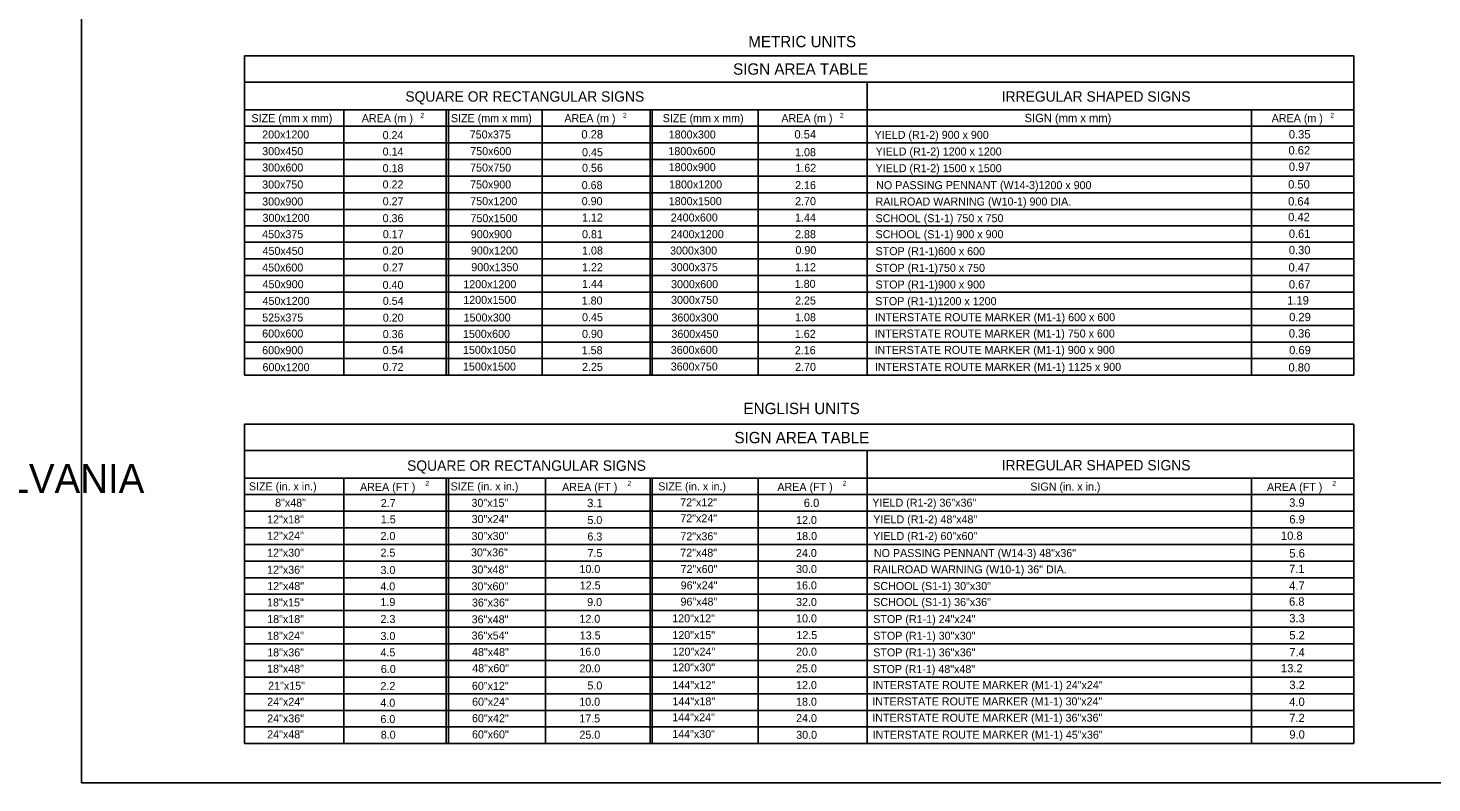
# Model space of a CAD drawing. Extents: x 644358 to 648627, y 294594 to 295782.
# Drawn here: x 645219 to 645745, y 295203 to 295486 of the extents above; entities that cross this region are included whole.
import ezdxf

# ---------------------------------------------------------------- set-up
doc = ezdxf.new("R2010")
doc.units = 0
for name, color, linetype in [('1', 7, 'Continuous'), ('2', 7, 'Continuous'), ('4', 7, 'Continuous')]:
    doc.layers.add(name, color=color, linetype=linetype)

msp = doc.modelspace()

# ---------------------------------------------------------------- linework, layer by layer
at = {"layer": '1'}
for p, q in [((645239.31, 295766.63), (645239.31, 295202.63)), ((646025.31, 295202.63), (645239.31, 295202.63)), ((645239.31, 295202.63), (645825.31, 295202.63))]:
    msp.add_line(p, q, dxfattribs=at)
at = {"layer": '2'}
for p, q in [((645300.44, 295475.25), (645300.44, 295355.5)), ((645716.19, 295475.25), (645300.44, 295475.25)), ((645716.19, 295355.5), (645716.19, 295475.25)), ((645716.19, 295465.37), (645300.44, 295465.37)), ((645533.81, 295465.37), (645533.81, 295355.5)), ((645300.44, 295455), (645716.19, 295455)), ((645337.69, 295455), (645337.69, 295355.5)), ((645376.06, 295455), (645376.06, 295355.5)), ((645376.94, 295455), (645376.94, 295355.5)), ((645411.94, 295455), (645411.94, 295355.5)), ((645452.44, 295455), (645452.44, 295355.5)), ((645453.19, 295455), (645453.19, 295355.5)), ((645492.94, 295455), (645492.94, 295355.5)), ((645677.81, 295355.5), (645677.81, 295455)), ((645300.44, 295448.87), (645716.19, 295448.87)), ((645300.44, 295442.62), (645716.19, 295442.62)), ((645300.44, 295436.37), (645716.19, 295436.37)), ((645300.44, 295430.12), (645716.19, 295430.12)), ((645300.44, 295423.87), (645716.19, 295423.87)), ((645300.44, 295417.62), (645716.19, 295417.62)), ((645300.44, 295411.5), (645716.19, 295411.5)), ((645300.44, 295405.37), (645716.19, 295405.37)), ((645300.44, 295399.12), (645716.19, 295399.12)), ((645300.44, 295392.87), (645716.19, 295392.87)), ((645300.44, 295386.62), (645716.19, 295386.62)), ((645300.44, 295380.37), (645716.19, 295380.37)), ((645300.44, 295374.12), (645716.19, 295374.12)), ((645533.81, 295374.12), (645716.19, 295374.12)), ((645300.44, 295367.87), (645716.19, 295367.87)), ((645716.19, 295367.87), (645533.81, 295367.87)), ((645300.44, 295361.75), (645716.19, 295361.75)), ((645300.44, 295355.5), (645533.81, 295355.5)), ((645716.19, 295355.5), (645533.81, 295355.5)), ((645300.44, 295337.19), (645300.44, 295217.44)), ((645716.19, 295337.19), (645300.44, 295337.19)), ((645716.19, 295217.44), (645716.19, 295337.19)), ((645716.19, 295327.31), (645300.44, 295327.31)), ((645533.81, 295327.31), (645533.81, 295217.44)), ((645300.44, 295316.94), (645716.19, 295316.94)), ((645337.69, 295316.94), (645337.69, 295217.44)), ((645376.06, 295316.94), (645376.06, 295217.44)), ((645376.94, 295316.94), (645376.94, 295217.44)), ((645413.24, 295316.94), (645413.24, 295217.44)), ((645452.44, 295316.94), (645452.44, 295217.44)), ((645453.19, 295316.94), (645453.19, 295217.44)), ((645492.94, 295316.94), (645492.94, 295217.44)), ((645677.81, 295217.44), (645677.81, 295316.94)), ((645300.44, 295310.81), (645716.19, 295310.81)), ((645300.44, 295304.56), (645716.19, 295304.56)), ((645300.44, 295298.31), (645716.19, 295298.31)), ((645300.44, 295292.06), (645716.19, 295292.06)), ((645300.44, 295285.81), (645716.19, 295285.81)), ((645300.44, 295279.56), (645716.19, 295279.56)), ((645300.44, 295273.44), (645716.19, 295273.44)), ((645300.44, 295267.31), (645716.19, 295267.31)), ((645300.44, 295261.06), (645716.19, 295261.06)), ((645300.44, 295254.81), (645716.19, 295254.81)), ((645300.44, 295248.56), (645716.19, 295248.56)), ((645300.44, 295242.31), (645716.19, 295242.31)), ((645300.44, 295236.06), (645716.19, 295236.06)), ((645533.81, 295236.06), (645716.19, 295236.06)), ((645300.44, 295229.81), (645716.19, 295229.81)), ((645716.19, 295229.81), (645533.81, 295229.81)), ((645300.44, 295223.69), (645716.19, 295223.69)), ((645300.44, 295217.44), (645533.81, 295217.44)), ((645716.19, 295217.44), (645533.81, 295217.44))]:
    msp.add_line(p, q, dxfattribs=at)
at = {"layer": '4'}
for p, q in [((645698.96, 295394.5), (645698.96, 295394.5)), ((645698.96, 295388.25), (645698.96, 295388.25)), ((645698.96, 295382), (645698.96, 295382)), ((645698.96, 295375.75), (645698.96, 295375.75)), ((645698.96, 295369.62), (645698.96, 295369.62)), ((645698.96, 295363.37), (645698.96, 295363.37)), ((645698.96, 295357.12), (645698.96, 295357.12)), ((645354.89, 295231.31), (645354.89, 295231.31)), ((645354.89, 295225.06), (645354.89, 295225.06)), ((645354.89, 295218.81), (645354.89, 295218.81))]:
    msp.add_line(p, q, dxfattribs=at)

# ---------------------------------------------------------------- texts
at = {"layer": '1'}
msp.add_text('COMMONWEALTH OF PENNSYLVANIA', height=10.7828, dxfattribs=at).set_placement((644996.9, 295311.36))
at = {"layer": '4'}
for s, height, p in [('METRIC UNITS', 4.25, (645489.24, 295478.46)), ('SIGN AREA TABLE', 4.25, (645483.55, 295468.17)), ('SQUARE OR RECTANGULAR SIGNS', 3.8872, (645360.71, 295458.05)), ('IRREGULAR SHAPED SIGNS', 3.8872, (645584.22, 295458.05)), ('SIZE (mm x mm)', 3, (645303.06, 295450.37)), ('AREA (m )', 3, (645344.39, 295450.37)), ('2', 1.8, (645366.34, 295452.06)), ('SIZE (mm x mm)', 3, (645377.81, 295450.37)), ('AREA (m )', 3, (645420.31, 295450.37)), ('2', 1.8, (645442.26, 295452.06)), ('SIZE (mm x mm)', 3, (645457.19, 295450.37)), ('AREA (m )', 3, (645501.66, 295450.37)), ('2', 1.8, (645523.61, 295452.06)), ('SIGN (mm x mm)', 3.1252, (645592.81, 295450.37)), ('AREA (m )', 3, (645685.43, 295450.37)), ('2', 1.8, (645707.38, 295452.06)), ('200x1200', 3, (645307.06, 295444.25)), ('0.24', 3, (645352.2, 295444)), ('750x375', 3, (645384.85, 295444.25)), ('0.28', 3.125, (645426.69, 295444.25)), ('1800x300', 3, (645459.44, 295444.25)), ('0.54', 3.125, (645506.54, 295444.25)), ('YIELD (R1-2) 900 x 900 ', 3, (645536.56, 295444.12)), ('0.35', 3.125, (645691.83, 295444.25)), ('0.62', 3.125, (645691.71, 295438.25)), ('300x450', 3, (645307.06, 295438)), ('0.14', 3, (645352.2, 295437.84)), ('750x600', 3, (645385.04, 295438)), ('0.45', 3, (645426.94, 295437.62)), ('1800x600', 3, (645459.31, 295438)), ('1.08', 3, (645506.79, 295437.62)), ('YIELD (R1-2) 1200 x 1200 ', 3, (645536.94, 295437.87)), ('300x600', 3, (645307.06, 295431.87)), ('0.18', 3, (645352.2, 295431.62)), ('750x750', 3, (645384.99, 295431.83)), ('0.56', 3, (645426.94, 295431.75)), ('1800x900', 3, (645459.44, 295432)), ('1.62', 3, (645506.9, 295431.75)), ('YIELD (R1-2) 1500 x 1500 ', 3, (645536.94, 295431.62)), ('0.97', 3.125, (645691.83, 295432.12)), ('300x750', 3, (645307.06, 295425.5)), ('0.22', 3, (645352.19, 295425.52)), ('750x900', 3, (645384.99, 295425.5)), ('0.68', 3, (645426.81, 295425.25)), ('1800x1200', 3, (645459.56, 295425.5)), ('2.16', 3, (645506.8, 295425.25)), ('NO PASSING PENNANT (W14-3)1200 x 900 ', 3, (645537.19, 295425.25)), ('0.50', 3.125, (645691.58, 295425.5)), ('300x900', 3, (645307.06, 295419.12)), ('0.27', 3, (645352.22, 295419.2)), ('750x1200', 3, (645385.04, 295419.25)), ('0.90', 3, (645426.81, 295419.25)), ('1800x1500', 3, (645459.44, 295419.25)), ('2.70', 3, (645506.8, 295419.25)), ('RAILROAD WARNING (W10-1) 900 DIA.', 3, (645536.94, 295419.12)), ('0.64', 3.125, (645691.58, 295419.12)), ('300x1200', 3, (645307.19, 295413)), ('0.36', 3, (645352.2, 295412.87)), ('750x1500', 3, (645385.13, 295412.86)), ('1.12', 3, (645426.94, 295413.12)), ('2400x600', 3, (645460.19, 295413.12)), ('1.44', 3, (645506.79, 295413.12)), ('SCHOOL (S1-1) 750 x 750 ', 3, (645536.94, 295412.87)), ('0.42', 3.125, (645691.58, 295413.25)), ('450x375', 3, (645307.06, 295406.87)), ('0.17', 3, (645352.26, 295406.87)), ('900x900', 3, (645385.25, 295406.87)), ('0.81', 3, (645426.94, 295406.87)), ('2400x1200', 3, (645460.19, 295406.87)), ('2.88', 3, (645506.79, 295406.87)), ('SCHOOL (S1-1) 900 x 900 ', 3, (645536.94, 295406.87)), ('0.61', 3.125, (645691.83, 295407)), ('450x450', 3, (645307.19, 295400.62)), ('0.20', 3, (645352.19, 295400.75)), ('900x1200', 3, (645385.29, 295400.75)), ('1.08', 3, (645426.94, 295400.75)), ('3000x300', 3, (645459.94, 295400.75)), ('0.90', 3, (645506.93, 295400.88)), ('STOP (R1-1)600 x 600 ', 3, (645536.94, 295400.5)), ('0.30', 3.125, (645691.83, 295400.87)), ('450x600', 3, (645307.06, 295394.37)), ('0.27', 3, (645352.26, 295394.39)), ('900x1350', 3, (645385.43, 295394.5)), ('1.22', 3, (645426.94, 295394.5)), ('3000x375', 3, (645460.19, 295394.5)), ('1.12', 3, (645506.79, 295394.5)), ('STOP (R1-1)750 x 750', 3, (645536.94, 295394.25)), ('0.47', 3.125, (645691.71, 295394.37)), ('450x900', 3, (645307.19, 295388.12)), ('0.40', 3, (645352.19, 295387.87)), ('1200x1200', 3, (645382.44, 295388.12)), ('1.44', 3, (645426.94, 295388.25)), ('3000x600', 3, (645460.31, 295388.12)), ('1.80', 3, (645506.67, 295388.25)), ('STOP (R1-1)900 x 900 ', 3, (645536.94, 295388)), ('0.67', 3.125, (645691.83, 295388)), ('450x1200', 3, (645307.19, 295381.87)), ('0.54', 3, (645352.26, 295381.88)), ('1200x1500', 3, (645382.44, 295382.25)), ('1.80', 3, (645426.81, 295382)), ('3000x750', 3, (645460.31, 295382.25)), ('2.25', 3, (645506.79, 295382)), ('STOP (R1-1)1200 x 1200', 3, (645536.81, 295381.75)), ('1.19', 3.125, (645691.21, 295382)), ('525x375', 3, (645307.06, 295375.62)), ('0.20', 3, (645352.26, 295375.57)), ('1500x300', 3, (645382.56, 295375.62)), ('0.45', 3, (645426.94, 295375.75)), ('3600x300', 3, (645460.44, 295375.62)), ('1.08', 3, (645506.79, 295375.75)), ('INTERSTATE ROUTE MARKER (M1-1) 600 x 600 ', 3, (645536.69, 295375.75)), ('0.29', 3.125, (645691.96, 295375.75)), ('600x600', 3, (645307.06, 295369.62)), ('0.36', 3, (645352.24, 295369.41)), ('1500x600', 3, (645382.31, 295369.5)), ('0.90', 3, (645426.93, 295369.5)), ('3600x450', 3, (645460.44, 295369.5)), ('1.62', 3, (645506.69, 295369.5)), ('INTERSTATE ROUTE MARKER (M1-1) 750 x 600 ', 3, (645536.56, 295369.62)), ('0.36', 3.125, (645691.83, 295369.62)), ('600x900', 3, (645307.06, 295363.37)), ('0.54', 3, (645352.22, 295363.39)), ('1500x1050', 3, (645382.31, 295363.5)), ('1.58', 3, (645426.81, 295363.37)), ('3600x600', 3, (645460.19, 295363.5)), ('2.16', 3, (645506.69, 295363.37)), ('INTERSTATE ROUTE MARKER (M1-1) 900 x 900 ', 3, (645536.56, 295363.5)), ('0.69', 3.125, (645691.96, 295363.37)), ('600x1200', 3, (645307.19, 295357)), ('0.72', 3, (645352.22, 295357.09)), ('1500x1500', 3, (645382.31, 295357.25)), ('2.25', 3, (645426.94, 295357.12)), ('3600x750', 3, (645460.19, 295357.25)), ('2.70', 3, (645506.8, 295357.12)), ('INTERSTATE ROUTE MARKER (M1-1) 1125 x 900 ', 3, (645536.69, 295357.12)), ('0.80', 3.125, (645691.71, 295356.87)), ('ENGLISH UNITS', 4.25, (645487.45, 295340.91)), ('SIGN AREA TABLE', 4.25, (645484.06, 295329.98)), ('SQUARE OR RECTANGULAR SIGNS', 3.8872, (645361.36, 295319.67)), ('IRREGULAR SHAPED SIGNS', 3.8872, (645584.22, 295319.81)), ('SIZE (in. x in.)', 3, (645302.07, 295312.31)), ('AREA (FT )', 3, (645343.73, 295312.11)), ('2', 1.8, (645368.22, 295314.08)), ('SIZE (in. x in.)', 3, (645377.67, 295312.31)), ('AREA (FT )', 3, (645419.46, 295312.11)), ('2', 1.8, (645443.95, 295314.08)), ('SIZE (in. x in.)', 3, (645455.5, 295312.31)), ('AREA (FT )', 3, (645500.16, 295312.11)), ('2', 1.8, (645524.65, 295314.08)), ('SIGN (in. x in.)', 3, (645594.95, 295312.24)), ('AREA (FT )', 3, (645683.68, 295312.11)), ('2', 1.8, (645708.17, 295314.08)), ('8"x48"', 3, (645311.91, 295306.19)), ('2.7', 3, (645351.5, 295306.07)), ('30"x15"', 3, (645385.5, 295306.15)), ('3.1', 3.125, (645428.86, 295306.02)), ('72"x12"', 3, (645463.75, 295306.32)), ('6.0', 3.125, (645510.05, 295306.08)), ('YIELD (R1-2) 36"x36" ', 3, (645535.72, 295306.2)), ('3.9', 3.125, (645691.98, 295306.18)), ('12"x18"', 3, (645308.91, 295299.94)), ('1.5', 3, (645351.53, 295299.96)), ('30"x24"', 3, (645385.56, 295300.07)), ('5.0', 3, (645428.96, 295299.7)), ('72"x24"', 3, (645463.77, 295300.36)), ('12.0', 3, (645507.16, 295299.7)), ('YIELD (R1-2) 48"x48" ', 3, (645536.09, 295299.95)), ('6.9', 3.125, (645692.01, 295299.9)), ('12"x24"', 3, (645308.91, 295293.81)), ('2.0', 3, (645351.4, 295293.7)), ('30"x30"', 3, (645385.51, 295293.72)), ('6.3', 3, (645428.96, 295293.52)), ('72"x36"', 3, (645463.79, 295293.61)), ('18.0', 3, (645507.21, 295293.7)), ('YIELD (R1-2) 60"x60" ', 3, (645536.09, 295293.7)), ('10.8', 3.125, (645688.89, 295293.77)), ('12"x30"', 3, (645308.91, 295287.44)), ('2.5', 3, (645351.4, 295287.45)), ('30"x36"', 3, (645385.33, 295287.57)), ('7.5', 3, (645429, 295287.32)), ('72"x48"', 3, (645463.76, 295287.45)), ('24.0', 3, (645507.12, 295287.32)), ('NO PASSING PENNANT (W14-3) 48"x36" ', 3, (645536.34, 295287.32)), ('5.6', 3.125, (645692.03, 295287.15)), ('12"x36"', 3, (645308.91, 295281.06)), ('3.0', 3, (645351.39, 295280.95)), ('30"x48"', 3, (645385.49, 295281.15)), ('10.0', 3, (645425.97, 295281.32)), ('72"x60"', 3, (645463.88, 295281.33)), ('30.0', 3, (645507.17, 295281.32)), ('RAILROAD WARNING (W10-1) 36" DIA.', 3, (645536.09, 295281.2)), ('7.1', 3.125, (645691.93, 295281.34)), ('12.5', 3, (645426.09, 295275.2)), ('96"x24"', 3, (645463.9, 295275.21)), ('16.0', 3, (645507.16, 295275.2)), ('12"x48"', 3, (645308.96, 295274.94)), ('4.0', 3, (645351.35, 295274.81)), ('30"x60"', 3, (645385.49, 295274.85)), ('SCHOOL (S1-1) 30"x30" ', 3, (645536.09, 295274.95)), ('4.7', 3.125, (645691.98, 295275.04)), ('18"x15"', 3, (645308.88, 295268.81)), ('1.9', 3, (645351.38, 295268.95)), ('36"x36"', 3, (645385.68, 295268.77)), ('9.0', 3, (645428.87, 295268.95)), ('96"x48"', 3, (645463.85, 295269.09)), ('32.0', 3, (645507.16, 295268.95)), ('SCHOOL (S1-1) 36"x36" ', 3, (645536.09, 295268.95)), ('6.8', 3.125, (645691.92, 295269.07)), ('18"x18"', 3, (645308.94, 295262.56)), ('2.3', 3, (645351.4, 295262.58)), ('36"x48"', 3, (645385.56, 295262.47)), ('12.0', 3, (645425.96, 295262.67)), ('120"x12"', 3, (645460.74, 295262.83)), ('10.0', 3, (645507.17, 295262.82)), ('STOP (R1-1) 24"x24" ', 3, (645536.09, 295262.57)), ('3.3', 3.125, (645692.01, 295262.81)), ('18"x24"', 3, (645308.91, 295256.31)), ('3.0', 3, (645351.4, 295256.2)), ('36"x54"', 3, (645385.56, 295256.4)), ('13.5', 3, (645426.09, 295256.42)), ('120"x15"', 3, (645460.79, 295256.58)), ('12.5', 3, (645507.29, 295256.57)), ('STOP (R1-1) 30"x30"', 3, (645536.09, 295256.32)), ('5.2', 3.125, (645692.02, 295256.45)), ('18"x36"', 3, (645308.94, 295250.06)), ('4.5', 3, (645351.4, 295250.08)), ('48"x48"', 3, (645385.71, 295250.2)), ('16.0', 3, (645425.96, 295250.32)), ('120"x24"', 3, (645460.85, 295250.34)), ('20.0', 3, (645507.17, 295250.32)), ('STOP (R1-1) 36"x36" ', 3, (645536.09, 295250.07)), ('7.4', 3.125, (645692.02, 295250.07)), ('18"x48"', 3, (645308.9, 295243.96)), ('6.0', 3, (645351.53, 295243.84)), ('48"x60"', 3, (645385.79, 295244.15)), ('20.0', 3, (645425.97, 295244.07)), ('120"x30"', 3, (645460.78, 295244.46)), ('25.0', 3, (645507.16, 295244.07)), ('STOP (R1-1) 48"x48"', 3, (645535.97, 295243.82)), ('13.2', 3.125, (645688.9, 295244.07)), ('21"x15"', 3, (645309.3, 295237.56)), ('2.2', 3, (645351.39, 295237.45)), ('60"x12"', 3, (645385.66, 295237.52)), ('5.0', 3, (645428.96, 295237.67)), ('144"x12"', 3, (645460.83, 295237.84)), ('12.0', 3, (645507.16, 295237.82)), ('INTERSTATE ROUTE MARKER (M1-1) 24"x24" ', 3, (645535.84, 295237.82)), ('3.2', 3.125, (645692.04, 295237.82)), ('24"x24"', 3, (645308.95, 295231.56)), ('4.0', 3, (645351.36, 295231.19)), ('60"x24"', 3, (645385.73, 295231.57)), ('10.0', 3, (645425.9, 295231.57)), ('144"x18"', 3, (645460.83, 295231.71)), ('18.0', 3, (645507.16, 295231.57)), ('INTERSTATE ROUTE MARKER (M1-1) 30"x24" ', 3, (645535.72, 295231.7)), ('4.0', 3.125, (645691.99, 295231.49)), ('24"x36"', 3, (645308.95, 295225.31)), ('6.0', 3, (645351.37, 295225.06)), ('60"x42"', 3, (645385.69, 295225.4)), ('17.5', 3, (645425.91, 295225.3)), ('144"x24"', 3, (645460.73, 295225.71)), ('24.0', 3, (645507.18, 295225.45)), ('INTERSTATE ROUTE MARKER (M1-1) 36"x36" ', 3, (645535.72, 295225.57)), ('7.2', 3.125, (645691.99, 295225.45)), ('24"x48"', 3, (645308.94, 295219.33)), ('8.0', 3, (645351.5, 295219.21)), ('60"x60"', 3, (645385.69, 295219.32)), ('25.0', 3, (645425.96, 295219.2)), ('144"x30"', 3, (645460.73, 295219.46)), ('30.0', 3, (645507.21, 295219.17)), ('INTERSTATE ROUTE MARKER (M1-1) 45"x36" ', 3, (645535.84, 295219.2)), ('9.0', 3.125, (645692.03, 295219.23))]:
    msp.add_text(s, height=height, dxfattribs=at).set_placement(p)

doc.saveas('drawing.dxf')
